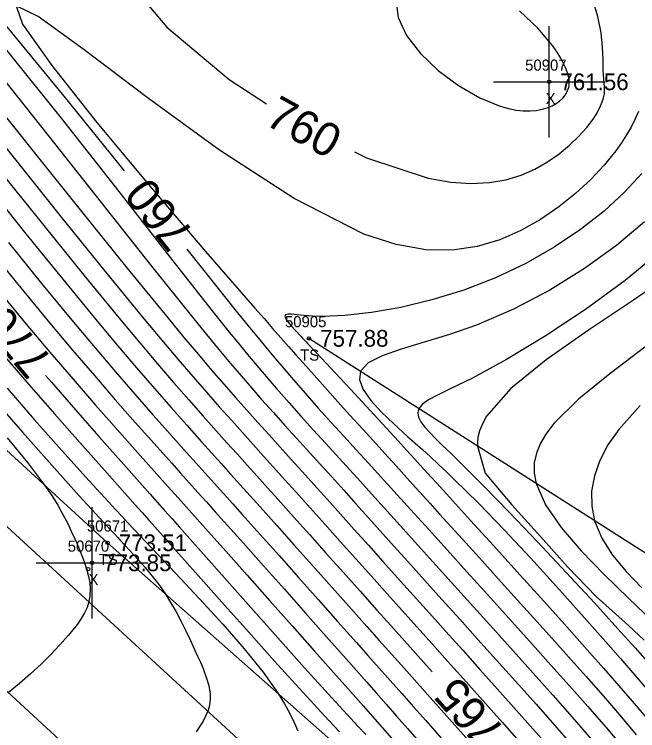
# Model space of a CAD drawing. Extents: x 1378535 to 1380697, y 997729 to 1000024.
# Drawn here: x 1378959.7 to 1379015.6, y 999615.5 to 999679.8 of the extents above; entities that cross this region are included whole.
import ezdxf

# ---------------------------------------------------------------- set-up
doc = ezdxf.new("R2010")
doc.units = 0
for name, color, linetype in [('RD_DTM_BkLn1', 7, 'Continuous'), ('RD_DTM_BkLn2', 7, 'Continuous'), ('RD_DTM_BkLn_txCode', 7, 'Continuous'), ('RD_DTM_Major1', 7, 'Continuous'), ('RD_DTM_Major1_Lbl', 7, 'Continuous'), ('RD_DTM_Minor1', 7, 'Continuous'), ('RD_EX_Misc', 7, 'Continuous'), ('RD_EX_Misc_txCode', 7, 'Continuous'), ('RD_EX_Road', 7, 'Continuous'), ('RD_EX_TX_Misc_ELEV', 7, 'Continuous'), ('RD_SMD_Locator', 7, 'Continuous')]:
    doc.layers.add(name, color=color, linetype=linetype)

msp = doc.modelspace()

# ---------------------------------------------------------------- linework, layer by layer
at = {"layer": 'RD_DTM_BkLn1'}
msp.add_lwpolyline([(1379201.7, 999398.205), (1379156.533, 999438.891), (1379112.084, 999479.847), (1379066.495, 999520.561), (1379020.821, 999562.613), (1378974.239, 999604.981), (1378928.957, 999646.778), (1378882.739, 999688.619), (1378834.578, 999733.071), (1378787.698, 999775.121), (1378743.642, 999816.274), (1378698.706, 999856.431), (1378652.056, 999898.787), (1378607.023, 999939.646), (1378604.538, 999941.267)], dxfattribs=at)
at = {"layer": 'RD_DTM_BkLn2'}
msp.add_line((1379024.868, 999625.97), (1378986.109, 999650.749), dxfattribs=at)
msp.add_lwpolyline([(1379093.966, 999521.58), (1379054.373, 999559.565), (1379010.103, 999595.197), (1378968.034, 999632.397), (1378925.231, 999671.641)], dxfattribs=at)
at = {"layer": 'RD_DTM_Major1'}
for points in [[(1378968.964, 999683.912), (1378973.359, 999678.697), (1378978.939, 999673.975), (1378982.296, 999671.802)], [(1379012.623, 999672.707), (1379012.635, 999673.015), (1379012.627, 999673.328), (1379012.606, 999673.657), (1379012.578, 999674.012), (1379012.549, 999674.4), (1379012.525, 999674.833), (1379012.499, 999675.775), (1379012.451, 999676.896), (1379012.318, 999678.191), (1379012.038, 999679.654), (1379011.549, 999681.281)], [(1378958.282, 999679.566), (1378964.118, 999672.482), (1378969.516, 999665.783)], [(1378990.179, 999667.49), (1378991.263, 999666.958), (1378996.807, 999665.136), (1378998.825, 999664.779), (1379000.648, 999664.653), (1379002.296, 999664.732), (1379003.789, 999664.991), (1379005.146, 999665.405), (1379006.387, 999665.948), (1379007.525, 999666.595), (1379008.564, 999667.319), (1379009.497, 999668.092), (1379010.322, 999668.889), (1379011.033, 999669.681), (1379011.626, 999670.441), (1379011.883, 999670.852), (1379012.102, 999671.246), (1379012.283, 999671.626), (1379012.429, 999671.995), (1379012.542, 999672.354), (1379012.623, 999672.707)], [(1378958.542, 999665.557), (1378962.299, 999660.879), (1378965.907, 999656.417), (1378969.209, 999652.389), (1378970.922, 999650.336), (1378972.5, 999648.475), (1378973.96, 999646.778), (1378975.322, 999645.218), (1378976.602, 999643.769), (1378977.82, 999642.404), (1378978.744, 999641.375), (1378979.651, 999640.367), (1378980.553, 999639.368), (1378981.461, 999638.363), (1378982.384, 999637.339), (1378983.335, 999636.283), (1378984.725, 999634.733), (1378986.173, 999633.113), (1378987.661, 999631.444), (1378989.175, 999629.747), (1378990.696, 999628.041), (1378992.208, 999626.348), (1378993.44, 999624.97), (1378994.67, 999623.597), (1378995.911, 999622.212), (1378997.165, 999620.812)], [(1378975.133, 999658.751), (1378975.258, 999658.594), (1378979.702, 999653.049), (1378980.657, 999651.873), (1378981.536, 999650.8), (1378982.351, 999649.815), (1378983.114, 999648.902), (1378983.838, 999648.046), (1378984.536, 999647.231), (1378985.761, 999645.824), (1378986.946, 999644.486), (1378988.099, 999643.203), (1378989.227, 999641.962), (1378990.337, 999640.748), (1378991.437, 999639.546), (1378992.288, 999638.614), (1378993.147, 999637.669), (1378994.024, 999636.704), (1378995.869, 999634.668), (1378996.857, 999633.577), (1378998.513, 999631.748), (1379000.278, 999629.799), (1379002.122, 999627.759), (1379004.013, 999625.662), (1379005.922, 999623.537), (1379007.818, 999621.418), (1379009.483, 999619.545), (1379011.12, 999617.685), (1379012.735, 999615.825), (1379014.333, 999613.948)], [(1379019.14, 999656.885), (1379015.246, 999654.173), (1379011.206, 999651.476), (1379007.404, 999648.822), (1379004.225, 999646.239), (1379002.05, 999643.756), (1379001.792, 999643.316), (1379001.581, 999642.878), (1379001.418, 999642.438), (1379001.305, 999641.993), (1379001.243, 999641.542), (1379001.232, 999641.081), (1379001.911, 999638.633), (1379004.315, 999635.791), (1379006.877, 999632.945), (1379009.348, 999630.198), (1379011.894, 999627.583), (1379014.792, 999624.968), (1379016.2, 999623.661)], [(1378962.472, 999647.406), (1378962.993, 999646.801), (1378965.152, 999644.324), (1378967.248, 999641.942), (1378969.252, 999639.682), (1378971.13, 999637.572), (1378971.817, 999636.801), (1378972.488, 999636.048), (1378973.151, 999635.303), (1378973.815, 999634.557), (1378974.487, 999633.802), (1378975.174, 999633.027), (1378977.125, 999630.825), (1378979.2, 999628.48), (1378981.354, 999626.049), (1378983.541, 999623.592), (1378985.716, 999621.165), (1378987.831, 999618.827), (1378988.506, 999618.088), (1378989.175, 999617.358), (1378989.844, 999616.632), (1378990.518, 999615.902), (1378991.202, 999615.164)]]:
    msp.add_lwpolyline(points, dxfattribs=at)
at = {"layer": 'RD_DTM_Minor1'}
for points in [[(1379015.681, 999671.106), (1379015.367, 999670.407), (1379015.011, 999669.71), (1379014.608, 999669.01), (1379014.153, 999668.304), (1379013.641, 999667.586), (1379012.61, 999666.312), (1379011.404, 999665.025), (1379010.038, 999663.76), (1379008.525, 999662.549), (1379006.878, 999661.428), (1379005.112, 999660.43), (1379003.227, 999659.593), (1379001.201, 999658.981), (1378999.001, 999658.66), (1378996.593, 999658.697), (1378993.943, 999659.161), (1378991.019, 999660.116), (1378984.769, 999663.291), (1378978.07, 999667.647), (1378971.573, 999672.37), (1378965.931, 999676.645), (1378961.797, 999679.657), (1378959.824, 999680.592), (1378960.404, 999678.956), (1378963.035, 999675.242), (1378967.077, 999670.143), (1378971.889, 999664.351), (1378976.828, 999658.558), (1378981.253, 999653.454), (1378982.073, 999652.516), (1378982.845, 999651.636), (1378983.575, 999650.807), (1378984.266, 999650.023), (1378984.925, 999649.279), (1378985.555, 999648.569), (1378987.079, 999646.861), (1378988.472, 999645.309), (1378989.759, 999643.885), (1378990.961, 999642.559), (1378992.103, 999641.303), (1378993.207, 999640.088), (1378993.932, 999639.288), (1378994.662, 999638.483), (1378995.406, 999637.66), (1378996.983, 999635.916), (1378997.836, 999634.973), (1378999.546, 999633.085), (1379001.405, 999631.032), (1379003.367, 999628.863), (1379005.386, 999626.626), (1379007.414, 999624.369), (1379009.407, 999622.141), (1379010.974, 999620.376), (1379012.5, 999618.639), (1379013.999, 999616.907), (1379015.484, 999615.157)], [(1378993.955, 999680.707), (1378994.115, 999679.542), (1378994.86, 999677.933), (1378996.106, 999676.326), (1378997.712, 999674.805), (1378999.537, 999673.453), (1379001.44, 999672.353), (1379003.281, 999671.587), (1379004.005, 999671.383), (1379004.691, 999671.249), (1379005.338, 999671.179), (1379005.944, 999671.17), (1379006.506, 999671.216), (1379007.025, 999671.312), (1379007.496, 999671.453), (1379007.92, 999671.633), (1379008.293, 999671.843), (1379008.615, 999672.075), (1379008.882, 999672.323), (1379009.093, 999672.577), (1379009.186, 999672.719), (1379009.262, 999672.859), (1379009.324, 999672.998), (1379009.375, 999673.134), (1379009.417, 999673.267), (1379009.453, 999673.394)], [(1379009.453, 999673.394), (1379009.465, 999673.509), (1379009.472, 999673.623), (1379009.473, 999673.741), (1379009.465, 999673.867), (1379009.447, 999674.006), (1379009.418, 999674.161), (1379009.326, 999674.503), (1379009.18, 999674.911), (1379008.977, 999675.376), (1379008.709, 999675.891), (1379008.373, 999676.449), (1379007.963, 999677.042), (1379006.652, 999678.587), (1379004.995, 999680.16)], [(1378958.559, 999677.105), (1378963.863, 999670.507), (1378969.036, 999663.933), (1378973.769, 999657.87), (1378977.753, 999652.806), (1378978.839, 999651.45), (1378979.831, 999650.229), (1378980.746, 999649.119), (1378981.602, 999648.097), (1378982.414, 999647.142), (1378983.202, 999646.231), (1378984.316, 999644.962), (1378985.416, 999643.728), (1378986.508, 999642.519), (1378987.594, 999641.325), (1378989.765, 999638.947), (1378990.734, 999637.881), (1378991.715, 999636.798), (1378993.744, 999634.551), (1378994.808, 999633.372), (1378997.499, 999630.392), (1379000.88, 999626.648), (1379002.643, 999624.692), (1379004.43, 999622.702), (1379006.225, 999620.696), (1379007.986, 999618.717), (1379009.735, 999616.734), (1379011.468, 999614.742)], [(1378957.845, 999675.05), (1378962.702, 999668.971), (1378967.465, 999662.947), (1378971.869, 999657.371), (1378975.651, 999652.637), (1378976.896, 999651.106), (1378978.03, 999649.734), (1378979.072, 999648.491), (1378980.044, 999647.351), (1378980.965, 999646.287), (1378981.856, 999645.272), (1378982.909, 999644.086), (1378983.953, 999642.922), (1378984.994, 999641.771), (1378987.085, 999639.47), (1378988.144, 999638.303), (1378989.222, 999637.111), (1378990.319, 999635.894), (1378991.439, 999634.647), (1378993.767, 999632.055), (1378994.982, 999630.703), (1378996.486, 999629.034), (1378998.039, 999627.311), (1378999.637, 999625.539), (1379001.272, 999623.722), (1379002.938, 999621.866), (1379004.63, 999619.975), (1379006.483, 999617.893), (1379008.344, 999615.784), (1379010.198, 999613.657)], [(1378956.616, 999673.464), (1378961.101, 999667.861), (1378965.569, 999662.284), (1378969.772, 999657.07), (1378973.459, 999652.554), (1378974.887, 999650.835), (1378976.184, 999649.295), (1378977.373, 999647.902), (1378978.477, 999646.628), (1378979.518, 999645.441), (1378980.519, 999644.313), (1378981.526, 999643.186), (1378982.523, 999642.079), (1378983.515, 999640.981), (1378984.512, 999639.88), (1378985.519, 999638.768), (1378986.544, 999637.633), (1378987.725, 999636.322), (1378988.936, 999634.971), (1378990.176, 999633.586), (1378991.444, 999632.169), (1378992.737, 999630.724), (1378994.055, 999629.255), (1378995.472, 999627.677), (1378996.917, 999626.071), (1378998.393, 999624.43), (1378999.903, 999622.751), (1379001.449, 999621.027), (1379003.034, 999619.254), (1379004.975, 999617.072), (1379006.948, 999614.837)], [(1378955.677, 999671.873), (1378959.794, 999666.737), (1378963.911, 999661.607), (1378967.824, 999656.76), (1378971.331, 999652.475), (1378972.909, 999650.581), (1378974.349, 999648.876), (1378975.673, 999647.332), (1378976.904, 999645.917), (1378978.062, 999644.602), (1378979.17, 999643.358), (1378980.135, 999642.282), (1378981.085, 999641.226), (1378982.032, 999640.177), (1378983.95, 999638.056), (1378984.94, 999636.958), (1378986.225, 999635.527), (1378987.554, 999634.043), (1378988.917, 999632.517), (1378991.714, 999629.386), (1378993.13, 999627.802), (1378994.457, 999626.322), (1378995.794, 999624.833), (1378997.151, 999623.322), (1378998.538, 999621.777), (1378999.963, 999620.185), (1379001.437, 999618.534), (1379003.462, 999616.256), (1379005.546, 999613.894)], [(1379015.969, 999665.535), (1379014.439, 999663.86), (1379012.595, 999662.17), (1379010.476, 999660.512), (1379008.119, 999658.93), (1379005.563, 999657.47), (1379002.845, 999656.177), (1379000.007, 999655.087), (1378997.141, 999654.206), (1378994.342, 999653.532), (1378991.707, 999653.059), (1378989.33, 999652.785), (1378987.309, 999652.705), (1378986.422, 999652.735), (1378985.663, 999652.795), (1378985.037, 999652.861), (1378984.548, 999652.909), (1378984.202, 999652.917), (1378984.001, 999652.862), (1378983.948, 999652.728), (1378984.027, 999652.513), (1378984.224, 999652.221), (1378984.527, 999651.855), (1378984.922, 999651.417), (1378985.396, 999650.909), (1378985.507, 999650.792), (1378985.62, 999650.672), (1378985.737, 999650.549), (1378985.856, 999650.422), (1378985.978, 999650.293), (1378986.103, 999650.161), (1378987.218, 999648.977), (1378988.474, 999647.635), (1378989.831, 999646.179), (1378991.249, 999644.651), (1378992.688, 999643.094), (1378994.106, 999641.551), (1378994.867, 999640.72), (1378995.618, 999639.898), (1378996.369, 999639.073), (1378997.129, 999638.238), (1378997.905, 999637.383), (1378998.709, 999636.499), (1379000.617, 999634.396), (1379002.653, 999632.151), (1379004.766, 999629.815), (1379006.908, 999627.439), (1379009.031, 999625.074), (1379011.084, 999622.771), (1379012.527, 999621.141), (1379013.924, 999619.544), (1379015.295, 999617.952), (1379016.657, 999616.338)], [(1378957.306, 999664.352), (1378960.705, 999660.126), (1378964.003, 999656.054), (1378967.086, 999652.302), (1378968.923, 999650.107), (1378970.634, 999648.095), (1378972.232, 999646.243), (1378973.73, 999644.532), (1378975.139, 999642.941), (1378976.472, 999641.449), (1378977.355, 999640.466), (1378978.22, 999639.505), (1378979.078, 999638.553), (1378980.821, 999636.619), (1378981.729, 999635.609), (1378983.225, 999633.939), (1378984.793, 999632.181), (1378986.409, 999630.367), (1378989.682, 999626.691), (1378991.288, 999624.89), (1378992.421, 999623.621), (1378993.542, 999622.366), (1378994.667, 999621.106), (1378995.813, 999619.822), (1378996.997, 999618.493), (1378998.235, 999617.1), (1379000.412, 999614.64)], [(1379016.221, 999661.214), (1379013.698, 999659.081), (1379010.832, 999657.013), (1379007.719, 999655.083), (1379004.453, 999653.367), (1379001.131, 999651.939), (1378998.722, 999651.102), (1378996.441, 999650.402), (1378994.395, 999649.78), (1378992.69, 999649.178), (1378991.432, 999648.535), (1378990.73, 999647.795), (1378990.63, 999647.021), (1378990.963, 999646.143), (1378991.646, 999645.179), (1378992.594, 999644.146), (1378993.726, 999643.063), (1378994.956, 999641.948), (1378995.63, 999641.342), (1378996.312, 999640.727), (1378997.002, 999640.098), (1378997.702, 999639.452), (1378998.417, 999638.783), (1378999.146, 999638.088), (1379001.35, 999635.906), (1379003.647, 999633.529), (1379005.986, 999631.031), (1379008.314, 999628.481), (1379010.579, 999625.954), (1379012.727, 999623.52), (1379014.062, 999621.991), (1379015.346, 999620.503), (1379016.601, 999619.026)], [(1378959.128, 999659.352), (1378962.113, 999655.675), (1378964.962, 999652.215), (1378966.91, 999649.894), (1378968.75, 999647.736), (1378970.488, 999645.729), (1378972.127, 999643.86), (1378973.672, 999642.118), (1378975.128, 999640.491), (1378975.969, 999639.554), (1378976.791, 999638.64), (1378977.605, 999637.736), (1378978.424, 999636.826), (1378979.259, 999635.898), (1378980.122, 999634.937), (1378981.726, 999633.145), (1378983.419, 999631.247), (1378985.165, 999629.285), (1378986.929, 999627.301), (1378988.676, 999625.335), (1378990.371, 999623.428), (1378991.396, 999622.276), (1378992.402, 999621.144), (1378993.408, 999620.013), (1378994.428, 999618.863), (1378995.481, 999617.674), (1378996.582, 999616.427), (1378998.805, 999613.898)], [(1378957.568, 999658.559), (1378960.239, 999655.277), (1378962.841, 999652.126), (1378964.885, 999649.696), (1378966.849, 999647.4), (1378968.727, 999645.235), (1378970.513, 999643.202), (1378972.202, 999641.3), (1378973.788, 999639.528), (1378974.585, 999638.64), (1378975.362, 999637.775), (1378976.131, 999636.92), (1378976.904, 999636.061), (1378977.69, 999635.186), (1378978.503, 999634.281), (1378980.218, 999632.363), (1378982.036, 999630.325), (1378983.913, 999628.216), (1378985.804, 999626.086), (1378987.665, 999623.985), (1378989.454, 999621.963), (1378990.365, 999620.933), (1378991.256, 999619.922), (1378992.145, 999618.914), (1378993.044, 999617.89), (1378993.969, 999616.834), (1378994.935, 999615.728), (1378997.223, 999613.101)], [(1379017.728, 999658.61), (1379014.476, 999655.932), (1379010.929, 999653.337), (1379007.306, 999650.935), (1379003.828, 999648.837), (1379000.714, 999647.154), (1378999.529, 999646.575), (1378998.475, 999646.074), (1378997.573, 999645.631), (1378996.843, 999645.225), (1378996.305, 999644.834), (1378995.981, 999644.438), (1378995.883, 999644.068), (1378995.949, 999643.673), (1378996.16, 999643.248), (1378996.497, 999642.788), (1378996.941, 999642.288), (1378997.474, 999641.745), (1378997.79, 999641.433), (1378998.126, 999641.106), (1378998.481, 999640.763), (1378998.855, 999640.402), (1378999.248, 999640.022), (1378999.658, 999639.622), (1379001.748, 999637.538), (1379004.104, 999635.12), (1379006.622, 999632.481), (1379009.198, 999629.734), (1379011.728, 999626.992), (1379014.108, 999624.368), (1379015.401, 999622.917), (1379016.631, 999621.515)], [(1378958.384, 999654.858), (1378960.728, 999652.027), (1378962.853, 999649.508), (1378964.935, 999647.08), (1378966.955, 999644.758), (1378968.893, 999642.556), (1378970.732, 999640.485), (1378972.453, 999638.559), (1378973.197, 999637.729), (1378974.638, 999636.122), (1378976.083, 999634.51), (1378976.832, 999633.674), (1378978.646, 999631.642), (1378980.575, 999629.474), (1378982.575, 999627.223), (1378984.601, 999624.938), (1378986.609, 999622.671), (1378988.554, 999620.473), (1378989.371, 999619.549), (1378990.991, 999617.716), (1378991.816, 999616.781), (1378993.557, 999614.807)], [(1379016.257, 999649.96), (1379013.098, 999647.572), (1379010.305, 999645.289), (1379008.122, 999643.13), (1379007.416, 999642.224), (1379006.879, 999641.335), (1379006.513, 999640.452), (1379006.324, 999639.563), (1379006.312, 999638.657), (1379006.484, 999637.723), (1379007.326, 999635.797), (1379008.727, 999633.762), (1379010.537, 999631.659), (1379012.607, 999629.531), (1379014.789, 999627.419), (1379016.934, 999625.364)], [(1378958.698, 999649.238), (1378960.973, 999646.6), (1378963.265, 999643.973), (1378965.537, 999641.394), (1378967.749, 999638.898), (1378970.502, 999635.806), (1378971.132, 999635.099), (1378971.759, 999634.395), (1378973.026, 999632.972), (1378973.677, 999632.241), (1378975.923, 999629.716), (1378978.284, 999627.064), (1378980.676, 999624.385), (1378983.016, 999621.776), (1378985.221, 999619.339), (1378987.208, 999617.173), (1378987.557, 999616.796), (1378987.896, 999616.432), (1378988.858, 999615.404)], [(1378959.01, 999646.271), (1378961.456, 999643.472), (1378963.929, 999640.684), (1378966.381, 999637.964), (1378968.764, 999635.364), (1378969.309, 999634.778), (1378969.849, 999634.198), (1378970.387, 999633.623), (1378970.926, 999633.05), (1378971.467, 999632.475), (1378972.014, 999631.897), (1378974.141, 999629.65), (1378976.286, 999627.363), (1378978.365, 999625.087), (1378980.293, 999622.875), (1378981.983, 999620.78), (1378983.351, 999618.853), (1378983.912, 999617.932), (1378984.378, 999617.068), (1378984.767, 999616.257), (1378985.094, 999615.495)], [(1378957.697, 999645.364), (1378960.389, 999642.314), (1378963.026, 999639.358), (1378965.493, 999636.623), (1378967.676, 999634.236), (1378967.935, 999633.955), (1378968.188, 999633.681), (1378968.435, 999633.415), (1378968.675, 999633.156), (1378968.909, 999632.904), (1378969.138, 999632.658), (1378969.961, 999631.772), (1378970.714, 999630.948), (1378971.406, 999630.165), (1378972.043, 999629.4), (1378972.635, 999628.632), (1378973.187, 999627.84), (1378973.694, 999627.03), (1378974.174, 999626.191), (1378974.627, 999625.334), (1378975.055, 999624.476), (1378975.461, 999623.629), (1378975.844, 999622.807), (1378976.114, 999622.223), (1378976.366, 999621.659), (1378976.598, 999621.111), (1378976.803, 999620.579), (1378976.975, 999620.059), (1378977.11, 999619.55), (1378977.182, 999619.177), (1378977.227, 999618.806), (1378977.238, 999618.433), (1378977.211, 999618.055), (1378977.142, 999617.669), (1378977.026, 999617.271), (1378976.604, 999616.362), (1378975.984, 999615.408)], [(1379015.844, 999644.716), (1379013.91, 999642.577), (1379012.941, 999641.184), (1379012.21, 999639.789), (1379011.72, 999638.401), (1379011.475, 999637.028), (1379011.479, 999635.68), (1379011.735, 999634.366), (1379012.389, 999632.804), (1379013.359, 999631.291), (1379014.576, 999629.815), (1379015.967, 999628.361)], [(1378959.024, 999641.821), (1378960.856, 999639.6), (1378962.381, 999637.58), (1378963.02, 999636.636), (1378963.565, 999635.759), (1378964.03, 999634.941), (1378964.429, 999634.174), (1378964.777, 999633.45), (1378965.09, 999632.762), (1378965.261, 999632.372), (1378965.425, 999631.99), (1378965.581, 999631.614), (1378965.729, 999631.241), (1378965.869, 999630.869), (1378966, 999630.496), (1378966.179, 999629.931), (1378966.325, 999629.362), (1378966.428, 999628.79), (1378966.474, 999628.219), (1378966.453, 999627.649), (1378966.351, 999627.084), (1378966.187, 999626.587), (1378965.956, 999626.091), (1378965.665, 999625.594), (1378965.32, 999625.091), (1378964.928, 999624.579), (1378964.492, 999624.055), (1378963.754, 999623.223), (1378962.94, 999622.365), (1378962.06, 999621.496), (1378961.124, 999620.626), (1378960.142, 999619.767), (1378959.124, 999618.933)]]:
    msp.add_lwpolyline(points, dxfattribs=at)
at = {"layer": 'RD_EX_Misc'}
for p, q in [((1379007.665, 999668.782), (1379007.665, 999678.782)), ((1379002.665, 999673.782), (1379012.665, 999673.782)), ((1378966.637, 999625.593), (1378966.637, 999635.593)), ((1378961.637, 999630.593), (1378971.637, 999630.593))]:
    msp.add_line(p, q, dxfattribs=at)
at = {"layer": 'RD_EX_Road'}
msp.add_lwpolyline([(1379209.475, 999405.54), (1379163.997, 999446.485), (1379118.805, 999488.017), (1379074.408, 999528.841), (1379028.669, 999569.9), (1378981.979, 999612.718), (1378937.166, 999653.911), (1378890.129, 999696.785), (1378842.566, 999740.72), (1378794.879, 999783.075), (1378749.806, 999824.149), (1378706.231, 999863.66), (1378659.579, 999905.32), (1378614.058, 999947.757), (1378610.306, 999950.384)], dxfattribs=at)
at = {"layer": 'RD_SMD_Locator'}
for centre in [(1379007.665, 999673.782), (1378986.109, 999650.749), (1378968.034, 999632.397), (1378966.637, 999630.593), (1378966.297, 999630.037)]:
    msp.add_circle(centre, 0.15, dxfattribs=at)

# ---------------------------------------------------------------- texts
at = {"layer": 'RD_DTM_BkLn_txCode'}
for s, p in [('50905', (1378983.952, 999651.749)), ('TS', (1378985.314, 999648.749)), ('50671', (1378966.176, 999633.397)), ('TS', (1378967.239, 999630.397))]:
    msp.add_text(s, height=1, dxfattribs=at).set_placement(p)
at = {"layer": 'RD_DTM_Major1_Lbl'}
for s, rotation, p in [('760', 331.32123, (1378982.022, 999670.018)), ('760', 128.61498, (1378975.915, 999660.177)), ('770', 130.20584, (1378963.21, 999648.819)), ('765', 131.61444, (1379003.854, 999615.553))]:
    msp.add_text(s, height=3, rotation=rotation, dxfattribs=at).set_placement(p)
at = {"layer": 'RD_EX_Misc_txCode'}
for s, p in [('50907', (1379005.508, 999674.782)), ('X', (1379007.35, 999671.782)), ('50670', (1378964.456, 999631.593)), ('X', (1378966.322, 999628.593))]:
    msp.add_text(s, height=1, dxfattribs=at).set_placement(p)
at = {"layer": 'RD_EX_TX_Misc_ELEV'}
for s, p in [('761.56', (1379008.665, 999673.032)), ('757.88', (1378987.109, 999649.999)), ('773.51', (1378969.034, 999631.647)), ('773.85', (1378967.637, 999629.843))]:
    msp.add_text(s, height=1.5, dxfattribs=at).set_placement(p)

doc.saveas('drawing.dxf')
